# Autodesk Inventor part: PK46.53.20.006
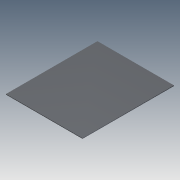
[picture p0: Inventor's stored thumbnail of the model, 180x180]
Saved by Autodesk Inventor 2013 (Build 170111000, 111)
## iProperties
Created: 2005-06
Part Number: PK46.53.20.006
Material: Steel, Mild
Document SubType Name: Modeling
Designer: HKostja
Manufacturer: Standard
Standards Organization: Custom
Density: 7.86 g/cm^3
Mass: 4737.22 g
Surface Area: 4072 cm^2
Volume: 602.7 cm^3
Author: HKostja
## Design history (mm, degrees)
sketch "Эскиз1"
  geometry: L1 (0, 0)-(-410, 0); L2 (-410, 0)-(-410, 490); L3 (-410, 490)-(0, 490); L4 (0, 490)-(0, 0)
  constraints: 8 end point, 2 parallel, 1 horizontal, 1 perpendicular, 1 other
  dimensions: "d0" = 410 distance of L1.start L1.end; "d1" = 490 distance of L3.end L1.start
extrude "Выдавливание1" new body sketch "Эскиз1" distance "d2" = 3; taper "d3" = 0 deg
body "Solid1"
